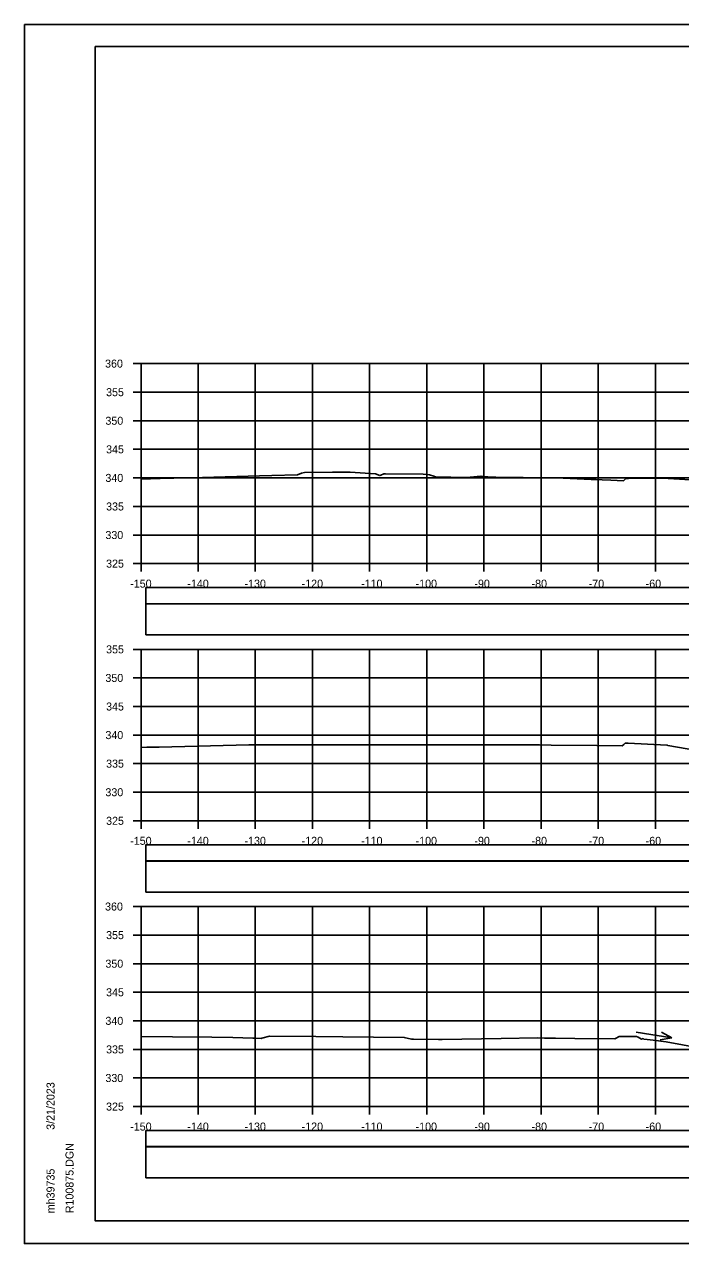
# Model space of a CAD drawing. Extents: x 1368122 to 1710785, y 373130 to 557566.
# Drawn here: x 1369185.2 to 1369300, y 373983.7 to 374197 of the extents above; entities that cross this region are included whole.
import ezdxf

# ---------------------------------------------------------------- set-up
doc = ezdxf.new("R2010")
doc.units = 0
for name, color, linetype in [('R_Axis', 7, 'Continuous'), ('R_Axis Annot', 7, 'Continuous'), ('R_Border', 7, 'Continuous'), ('R_Exist Surface', 7, 'Continuous'), ('R_Grid', 7, 'Continuous'), ('R_No Plot', 7, 'Continuous'), ('R_Water Annot', 7, 'Continuous')]:
    doc.layers.add(name, color=color, linetype=linetype)

msp = doc.modelspace()

# ---------------------------------------------------------------- linework, layer by layer
for points in [[(1369206.41, 374095.65), (1369504.71, 374095.65), (1369504.71, 374098.47), (1369206.41, 374098.47)], [(1369206.41, 374090.19), (1369504.71, 374090.19), (1369504.71, 374095.6), (1369206.41, 374095.6)], [(1369206.41, 374050.65), (1369504.71, 374050.65), (1369504.71, 374053.47), (1369206.41, 374053.47)], [(1369206.41, 374045.19), (1369504.71, 374045.19), (1369504.71, 374050.6), (1369206.41, 374050.6)], [(1369206.41, 374000.65), (1369504.71, 374000.65), (1369504.71, 374003.47), (1369206.41, 374003.47)], [(1369206.41, 373995.19), (1369504.71, 373995.19), (1369504.71, 374000.6), (1369206.41, 374000.6)]]:
    msp.add_lwpolyline(points, close=True)
at = {"layer": 'R_Axis'}
for p, q in [((1369204.16, 374137.66), (1369205.56, 374137.66)), ((1369205.56, 374102.66), (1369205.56, 374137.66)), ((1369204.16, 374132.66), (1369205.56, 374132.66)), ((1369204.16, 374127.66), (1369205.56, 374127.66)), ((1369204.16, 374122.66), (1369205.56, 374122.66)), ((1369204.16, 374117.66), (1369205.56, 374117.66)), ((1369204.16, 374112.66), (1369205.56, 374112.66)), ((1369204.16, 374107.66), (1369205.56, 374107.66)), ((1369204.16, 374102.66), (1369205.56, 374102.66)), ((1369205.56, 374102.66), (1369505.56, 374102.66)), ((1369205.56, 374101.26), (1369205.56, 374102.66)), ((1369215.56, 374101.26), (1369215.56, 374102.66)), ((1369225.56, 374101.26), (1369225.56, 374102.66)), ((1369235.56, 374101.26), (1369235.56, 374102.66)), ((1369245.56, 374101.26), (1369245.56, 374102.66)), ((1369255.56, 374101.26), (1369255.56, 374102.66)), ((1369265.56, 374101.26), (1369265.56, 374102.66)), ((1369275.56, 374101.26), (1369275.56, 374102.66)), ((1369285.56, 374101.26), (1369285.56, 374102.66)), ((1369295.56, 374101.26), (1369295.56, 374102.66)), ((1369204.16, 374087.66), (1369205.56, 374087.66)), ((1369205.56, 374057.66), (1369205.56, 374087.66)), ((1369204.16, 374082.66), (1369205.56, 374082.66)), ((1369204.16, 374077.66), (1369205.56, 374077.66)), ((1369204.16, 374072.66), (1369205.56, 374072.66)), ((1369204.16, 374067.66), (1369205.56, 374067.66)), ((1369204.16, 374062.66), (1369205.56, 374062.66)), ((1369204.16, 374057.66), (1369205.56, 374057.66)), ((1369205.56, 374057.66), (1369505.56, 374057.66)), ((1369205.56, 374056.26), (1369205.56, 374057.66)), ((1369215.56, 374056.26), (1369215.56, 374057.66)), ((1369225.56, 374056.26), (1369225.56, 374057.66)), ((1369235.56, 374056.26), (1369235.56, 374057.66)), ((1369245.56, 374056.26), (1369245.56, 374057.66)), ((1369255.56, 374056.26), (1369255.56, 374057.66)), ((1369265.56, 374056.26), (1369265.56, 374057.66)), ((1369275.56, 374056.26), (1369275.56, 374057.66)), ((1369285.56, 374056.26), (1369285.56, 374057.66)), ((1369295.56, 374056.26), (1369295.56, 374057.66)), ((1369204.16, 374042.66), (1369205.56, 374042.66)), ((1369205.56, 374007.66), (1369205.56, 374042.66)), ((1369204.16, 374037.66), (1369205.56, 374037.66)), ((1369204.16, 374032.66), (1369205.56, 374032.66)), ((1369204.16, 374027.66), (1369205.56, 374027.66)), ((1369204.16, 374022.66), (1369205.56, 374022.66)), ((1369204.16, 374017.66), (1369205.56, 374017.66)), ((1369204.16, 374012.66), (1369205.56, 374012.66)), ((1369204.16, 374007.66), (1369205.56, 374007.66)), ((1369205.56, 374007.66), (1369505.56, 374007.66)), ((1369205.56, 374006.26), (1369205.56, 374007.66)), ((1369215.56, 374006.26), (1369215.56, 374007.66)), ((1369225.56, 374006.26), (1369225.56, 374007.66)), ((1369235.56, 374006.26), (1369235.56, 374007.66)), ((1369245.56, 374006.26), (1369245.56, 374007.66)), ((1369255.56, 374006.26), (1369255.56, 374007.66)), ((1369265.56, 374006.26), (1369265.56, 374007.66)), ((1369275.56, 374006.26), (1369275.56, 374007.66)), ((1369285.56, 374006.26), (1369285.56, 374007.66)), ((1369295.56, 374006.26), (1369295.56, 374007.66))]:
    msp.add_line(p, q, dxfattribs=at)
at = {"layer": 'R_Border'}
for p, q in [((1369197.56, 374193.12), (1369513.74, 374193.12)), ((1369197.56, 373987.66), (1369197.56, 374193.12)), ((1369197.56, 373987.66), (1369197.56, 373987.66)), ((1369513.74, 373987.66), (1369197.56, 373987.66))]:
    msp.add_line(p, q, dxfattribs=at)
at = {"layer": 'R_Exist Surface'}
for points in [[(1369205.56, 374117.42), (1369208.91, 374117.54), (1369210.12, 374117.59), (1369211.3, 374117.64), (1369211.65, 374117.65), (1369216.33, 374117.76), (1369226.29, 374118.04), (1369228.44, 374118.06), (1369232.93, 374118.2), (1369233.63, 374118.47), (1369234.16, 374118.58), (1369239.04, 374118.69), (1369241.63, 374118.68), (1369242.16, 374118.67), (1369243.93, 374118.55), (1369246.58, 374118.37), (1369247.35, 374118.08), (1369247.52, 374118.14), (1369248.04, 374118.35), (1369248.32, 374118.35), (1369254.94, 374118.33), (1369256.05, 374118.21), (1369256.81, 374117.96), (1369257.07, 374117.83), (1369262.54, 374117.76), (1369265.02, 374117.98), (1369265.08, 374117.98), (1369266.85, 374117.77), (1369267.66, 374117.78), (1369269.83, 374117.76), (1369272.45, 374117.71), (1369279.44, 374117.6), (1369284.34, 374117.39), (1369285.2, 374117.37), (1369286.26, 374117.32), (1369287.77, 374117.24), (1369290, 374117.15), (1369290.07, 374117.22), (1369290.38, 374117.57), (1369290.75, 374117.57), (1369290.88, 374117.56), (1369293.39, 374117.59), (1369297.82, 374117.53), (1369302.68, 374117.25)], [(1369205.56, 374070.51), (1369206.56, 374070.54), (1369208.73, 374070.57), (1369224.45, 374070.97), (1369236.48, 374070.94), (1369256.52, 374070.95), (1369272.24, 374070.93), (1369275.27, 374070.93), (1369277.33, 374070.92), (1369285.34, 374070.86), (1369289.78, 374070.78), (1369290.04, 374070.99), (1369290.31, 374071.25), (1369290.58, 374071.25), (1369290.81, 374071.25), (1369297.58, 374070.88), (1369297.66, 374070.87), (1369297.73, 374070.86), (1369304.84, 374069.64)], [(1369205.56, 374019.89), (1369211.09, 374019.87), (1369217.94, 374019.78), (1369221.62, 374019.73), (1369225.11, 374019.6), (1369225.51, 374019.6), (1369226.56, 374019.57), (1369226.71, 374019.6), (1369228.02, 374019.98), (1369236.15, 374019.89), (1369240.9, 374019.84), (1369251.62, 374019.77), (1369252.88, 374019.48), (1369252.89, 374019.48), (1369253.24, 374019.48), (1369257.64, 374019.4), (1369258.24, 374019.41), (1369268.6, 374019.57), (1369274.92, 374019.66), (1369276.17, 374019.65), (1369278.08, 374019.62), (1369281.49, 374019.57), (1369288.48, 374019.49), (1369288.57, 374019.54), (1369289.25, 374019.92), (1369290.13, 374019.91), (1369290.14, 374019.91), (1369290.25, 374019.89), (1369290.47, 374019.91), (1369290.87, 374019.91), (1369292.25, 374019.89), (1369292.55, 374019.8), (1369293.15, 374019.48), (1369293.45, 374019.55), (1369293.54, 374019.48), (1369294.12, 374019.42), (1369295.2, 374019.27), (1369297.44, 374018.99), (1369303.16, 374017.96)]]:
    msp.add_lwpolyline(points, dxfattribs=at)
at = {"layer": 'R_Grid'}
for p, q in [((1369205.56, 374137.66), (1369505.56, 374137.66)), ((1369205.56, 374102.66), (1369205.56, 374137.66)), ((1369215.56, 374102.66), (1369215.56, 374137.66)), ((1369225.56, 374102.66), (1369225.56, 374137.66)), ((1369235.56, 374102.66), (1369235.56, 374137.66)), ((1369245.56, 374102.66), (1369245.56, 374137.66)), ((1369255.56, 374102.66), (1369255.56, 374137.66)), ((1369265.56, 374102.66), (1369265.56, 374137.66)), ((1369275.56, 374102.66), (1369275.56, 374137.66)), ((1369285.56, 374102.66), (1369285.56, 374137.66)), ((1369295.56, 374102.66), (1369295.56, 374137.66)), ((1369205.56, 374132.66), (1369505.56, 374132.66)), ((1369205.56, 374127.66), (1369505.56, 374127.66)), ((1369205.56, 374122.66), (1369505.56, 374122.66)), ((1369205.56, 374117.66), (1369505.56, 374117.66)), ((1369205.56, 374112.66), (1369505.56, 374112.66)), ((1369205.56, 374107.66), (1369505.56, 374107.66)), ((1369205.56, 374102.66), (1369505.56, 374102.66)), ((1369205.56, 374087.66), (1369505.56, 374087.66)), ((1369205.56, 374057.66), (1369205.56, 374087.66)), ((1369215.56, 374057.66), (1369215.56, 374087.66)), ((1369225.56, 374057.66), (1369225.56, 374087.66)), ((1369235.56, 374057.66), (1369235.56, 374087.66)), ((1369245.56, 374057.66), (1369245.56, 374087.66)), ((1369255.56, 374057.66), (1369255.56, 374087.66)), ((1369265.56, 374057.66), (1369265.56, 374087.66)), ((1369275.56, 374057.66), (1369275.56, 374087.66)), ((1369285.56, 374057.66), (1369285.56, 374087.66)), ((1369295.56, 374057.66), (1369295.56, 374087.66)), ((1369205.56, 374082.66), (1369505.56, 374082.66)), ((1369205.56, 374077.66), (1369505.56, 374077.66)), ((1369205.56, 374072.66), (1369505.56, 374072.66)), ((1369205.56, 374067.66), (1369505.56, 374067.66)), ((1369205.56, 374062.66), (1369505.56, 374062.66)), ((1369205.56, 374057.66), (1369505.56, 374057.66)), ((1369205.56, 374042.66), (1369505.56, 374042.66)), ((1369205.56, 374007.66), (1369205.56, 374042.66)), ((1369215.56, 374007.66), (1369215.56, 374042.66)), ((1369225.56, 374007.66), (1369225.56, 374042.66)), ((1369235.56, 374007.66), (1369235.56, 374042.66)), ((1369245.56, 374007.66), (1369245.56, 374042.66)), ((1369255.56, 374007.66), (1369255.56, 374042.66)), ((1369265.56, 374007.66), (1369265.56, 374042.66)), ((1369275.56, 374007.66), (1369275.56, 374042.66)), ((1369285.56, 374007.66), (1369285.56, 374042.66)), ((1369295.56, 374007.66), (1369295.56, 374042.66)), ((1369205.56, 374037.66), (1369505.56, 374037.66)), ((1369205.56, 374032.66), (1369505.56, 374032.66)), ((1369205.56, 374027.66), (1369505.56, 374027.66)), ((1369205.56, 374022.66), (1369505.56, 374022.66)), ((1369205.56, 374017.66), (1369505.56, 374017.66)), ((1369205.56, 374012.66), (1369505.56, 374012.66)), ((1369205.56, 374007.66), (1369505.56, 374007.66))]:
    msp.add_line(p, q, dxfattribs=at)
at = {"layer": 'R_No Plot'}
for p, q in [((1369185.16, 374197.02), (1369518.49, 374197.02)), ((1369185.16, 373983.68), (1369518.49, 373983.68))]:
    msp.add_line(p, q, dxfattribs=at)
for points in [[(1369185.15, 374197.02), (1369518.49, 374197.02), (1369518.49, 373983.68), (1369185.15, 373983.68)], [(1369431.48, 374193.12), (1369451.1, 374193.12), (1369451.1, 374183.24), (1369467.21, 374183.24), (1369490.41, 374183.24), (1369490.53, 374155.08), (1369513.74, 374155.08), (1369513.74, 373987.66), (1369197.56, 373987.66), (1369197.56, 374193.12)]]:
    msp.add_lwpolyline(points, close=True, dxfattribs=at)
at = {"layer": 'R_Water Annot'}
for p, q in [((1369292.21, 374020.68), (1369298.42, 374019.71)), ((1369298.42, 374019.71), (1369296.41, 374019.32)), ((1369298.42, 374019.71), (1369296.63, 374020.7))]:
    msp.add_line(p, q, dxfattribs=at)

# ---------------------------------------------------------------- texts
at = {"layer": 'R_Axis Annot'}
for s, p in [('360', (1369199.27, 374136.96)), ('355', (1369199.45, 374131.96)), ('350', (1369199.33, 374126.96)), ('345', (1369199.45, 374121.96)), ('340', (1369199.33, 374116.96)), ('335', (1369199.45, 374111.96)), ('330', (1369199.33, 374106.96)), ('325', (1369199.45, 374101.96)), ('-150', (1369203.67, 374098.46)), ('-140', (1369213.67, 374098.46)), ('-130', (1369223.67, 374098.46)), ('-120', (1369233.67, 374098.46)), ('-110', (1369244.07, 374098.46)), ('-100', (1369253.61, 374098.46)), ('-90', (1369263.9, 374098.46)), ('-80', (1369273.9, 374098.46)), ('-70', (1369283.9, 374098.46)), ('-60', (1369293.87, 374098.46)), ('355', (1369199.45, 374086.96)), ('350', (1369199.33, 374081.96)), ('345', (1369199.45, 374076.96)), ('340', (1369199.33, 374071.96)), ('335', (1369199.45, 374066.96)), ('330', (1369199.33, 374061.96)), ('325', (1369199.45, 374056.96)), ('-150', (1369203.67, 374053.46)), ('-140', (1369213.67, 374053.46)), ('-130', (1369223.67, 374053.46)), ('-120', (1369233.67, 374053.46)), ('-110', (1369244.07, 374053.46)), ('-100', (1369253.61, 374053.46)), ('-90', (1369263.9, 374053.46)), ('-80', (1369273.9, 374053.46)), ('-70', (1369283.9, 374053.46)), ('-60', (1369293.87, 374053.46)), ('360', (1369199.27, 374041.96)), ('355', (1369199.45, 374036.96)), ('350', (1369199.33, 374031.96)), ('345', (1369199.45, 374026.96)), ('340', (1369199.33, 374021.96)), ('335', (1369199.45, 374016.96)), ('330', (1369199.33, 374011.96)), ('325', (1369199.45, 374006.96)), ('-150', (1369203.67, 374003.46)), ('-140', (1369213.67, 374003.46)), ('-130', (1369223.67, 374003.46)), ('-120', (1369233.67, 374003.46)), ('-110', (1369244.07, 374003.46)), ('-100', (1369253.61, 374003.46)), ('-90', (1369263.9, 374003.46)), ('-80', (1369273.9, 374003.46)), ('-70', (1369283.9, 374003.46)), ('-60', (1369293.87, 374003.46))]:
    msp.add_text(s, height=1.4, dxfattribs=at).set_placement(p)
at = {"layer": 'R_Border'}
for s, p in [('3/21/2023', (1369190.43, 374003.59)), ('R100875.DGN', (1369193.75, 373988.99)), ('mh39735', (1369190.43, 373988.99))]:
    msp.add_text(s, height=1.4, rotation=90, dxfattribs=at).set_placement(p)

doc.saveas('drawing.dxf')
